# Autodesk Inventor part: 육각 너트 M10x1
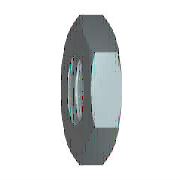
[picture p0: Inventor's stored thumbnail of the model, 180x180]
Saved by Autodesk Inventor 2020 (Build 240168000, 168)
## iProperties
Created: 2012-02
Part Number: 육각 너트 M10x1
Material: 스테인리스강
Description: 6각 가는 너트(모따기) - 제품 등급 A 및 B
Document SubType Name: Modeling
Standard: ISO 4035
Designer: mdu-01
Standard Revision: Third edition 1999-08-15
Standards Organization: ISO
Language: ko-KR
Size Designation: M10
Categories: <MemberInstance><Categories><Category DisplayName="조임쇠" InternalName="e4da775c-781d-43d5-af7c-5136215cf5a6" Mnemonic="FSTN"><Category DisplayName="너트" InternalN
Density: 7.75 g/cm^3
Appearance: 반광택
IsCustomPart: 1
Author: mdu-01
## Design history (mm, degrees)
sketch "스케치1"
  geometry: L1 (-9.238, 0)-(-4.619, 8); L2 (-4.619, 8)-(4.619, 8); L3 (4.619, 8)-(9.238, 0); L4 (9.238, 0)-(4.619, -8); L5 (4.619, -8)-(-4.619, -8); L6 (-4.619, -8)-(-9.238, 0); 2 further points
  constraints: 12 end point, 1 coincident, 1 horizontal, 11 other
  dimensions: "d0" = 18.47521 distance of L3.end L1.start (= 1.1547 x SW)
extrude "본체" new body sketch "스케치1" distance "d1" = 5 (= KOH); taper "d2" = 0 deg
sketch "스케치2"
  geometry: L1 (0, 4.619)-(0, 9.238) reference; L2 (0, 9.238)-(5, 9.238) reference; L3 (5, 4.619)-(5, 9.238) reference; L4 (-1, 0)-(6, 0) reference; L5 (1.119, 9.238)-(0, 7.3); L6 (3.881, 9.238)-(5, 7.3)
  constraints: 4 end point, 4 point on line
  dimensions: "d3" = 30 deg angle of L1 L5 (= ANG1); "d4" = 30 deg angle of L3 L6 (= ANG2); "d5" = 14.6 diameter of L5.end L4 (= SW0); "d6" = 14.6 diameter of L6.end L4 (= SW01)
revolve "모따기1" sketch "스케치2" stored, may be unused: angle "d7" = 90 deg
sketch "스케치3"
  geometry: 4 further points
  constraints: 1 coincident, 1 other
hole "스레드" sketch "스케치3" at (0, 0) diameter "d25" = 8.917; stored, may be unused: countersink angle "d29" = 82 deg, drill point angle "d31" = 118 deg; dims "d26" = 6, "d27" = 4, "d28" = 2, "d30" = 8
workaxis "Work Axis1"
workplane "Work Plane1"
body "Solid1"
chamfer "모따기2" distance "d8" = 0.8119 (= -0.5 x GD1 + 0.5 x NND); stored, may be unused: angle "d9" = 30 deg, second distance "d40" = 0.8119 (= -0.5 x GD1 + 0.5 x NND)
chamfer "모따기3" distance "d10" = 0.8119 (= -0.5 x GD1 + 0.5 x NND); stored, may be unused: angle "d11" = 30 deg, second distance "d41" = 0.8119 (= -0.5 x GD1 + 0.5 x NND)
other parameters: "ANG1" = 30 deg [user parameter; used in 1 equation term], "ANG2" = 30 deg [user parameter; used in 1 equation term], "KOH" = 5 [user parameter; used in 1 equation term], "SW" = 16 [user parameter; used in 2 equation terms], "SW0" = 14.6 [user parameter; used in 2 equation terms], "SW01" = 14.6 (= SW0) [user parameter; used in 1 equation term], "GD1" = 8.3762 (computed from THREADDIA, PTC, TOA) [user parameter; used in 4 equation terms], "d13" = 0, "d14" = 0, "d39" = 0, "d42" = 0, "GUL" = 0.8119 (= 0.541266 x PTC) [user parameter], "TPU" = 6.66667 (computed from PTC) [user parameter], "TOA" = 30 deg [user parameter; used in 1 equation term], "PTC" = 1.5 [user parameter; used in 4 equation terms], "E0" = 18.48 (= 1.155 x SW) [user parameter], "GAL" = 0.8119 (= 0.541266 x PTC) [user parameter]
